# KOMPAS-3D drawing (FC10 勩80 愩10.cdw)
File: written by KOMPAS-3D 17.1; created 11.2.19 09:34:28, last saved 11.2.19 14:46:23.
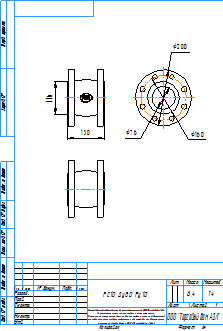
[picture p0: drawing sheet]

Sheet 1: A4, portrait

Title block, sheet 1: name: FC10 Ду80 Ру10; mass: 6,4; sheets: 1; sheet format: A4; stored path: \\adlc.lan\data\АДЛ_ПКД\3D-модели\ADL production\Гибкие вставки серии FC\FC10\KOMPAS 2D\FC10 Ду80 Ру10.cdw

Views: Вид 1
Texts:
  kka
  adl
  Рама для чертежей
  Лит-Масса-Масштаб
  Материал-Предприятие
  Масштаб
  Изм.
  Лист
  № докум.
  Подп.
  Дата
  Лит.
  Разраб.
  Пров.
  Т.контр.
  Листов
  Внимание! Данный продукт является объектом авторского права ООО «Торговый Дом АДЛ».
  Запрещается изменение, копирование, распространение
  (в том числе путем копирования на другие сайты и ресурсы в Интернете)
  или любое иное использование информации и объектов без предварительного
  согласия правообладателя (ООО «Торговый Дом АДЛ»).
  Н.контр.
  Утв.
  ООО "Торговый дом АДЛ"
  Изменение
  Номер документа
  Подпись
  Обозначение документа
  Наименование изделия
  Масса изделия по ГОСТ 2.109-73
  Порядковый номер листа
  Общее количество листов в документе
  Характер работы, выполненной лицом, подписавшим документ
  Наименование или индекс предприятия, выпускающего документ
  Инв. № подл.
  Подп. и дата
  Взам. инв. №
  Инв. № дубл.
  Инвентарный номер подлинника по ГОСТ 2.501-68
  Подпись принявшего подлинник в отдел технической документации
  Инвентарный номер подлинника, взамен которого выпущен данный подлинник
  Инвентарный номер дубликата по ГОСТ 2.502-68
  Подпись принявшего дубликат в отдел технической документации
  Справ. №
  Перв. примен.
  Обозначение документа, взамен или на основании которого выпущен данный документ
  Обозначение документа, в котором впервые записан данный документ
  Подпись лица, копировавшего чертеж
  Обозначение формата листа
  !Рама для чертежа
Dimensions and other numbers on the sheet: 130; 116; 76; 200; 160; 1:4; 1; 6,4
